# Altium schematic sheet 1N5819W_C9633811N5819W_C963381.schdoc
size 127 x 101 mm
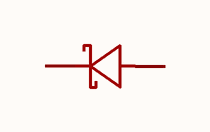
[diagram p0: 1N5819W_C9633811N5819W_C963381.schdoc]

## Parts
D?  1n5819w_c963381  [SOD-123_L2.7-W1.6-LS3.7-RD]  (value not drawn)

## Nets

Not connected (* = marked no-connect by the designer): D? 1(C) 2(A)

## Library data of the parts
D? = 1n5819w_c963381: 二极管配置:独立式;正向压降(Vf):600mV@200mA;直流反向耐压(Vr):40V;整流电流:350mA;; Manufacturer: JSMSEMI(杰盛微); AddInBom: yes; ModelId: ad7e39f9e5534b3c96ffdc5532ebb493; ModelName: SOD-123_L2.7-W1.6-H1.4-LS3.7; ModelTransform: 146.026,62.992,0,180,0,0,0.0005,0,0; Diode Configuration: 独立式; Voltage - DC Reverse(Vr): 40V; Current - Rectified: 350mA; Reverse Leakage Current (Ir): 5uA@30V; Non-Repetitive Peak Forward Surge Current: 13A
